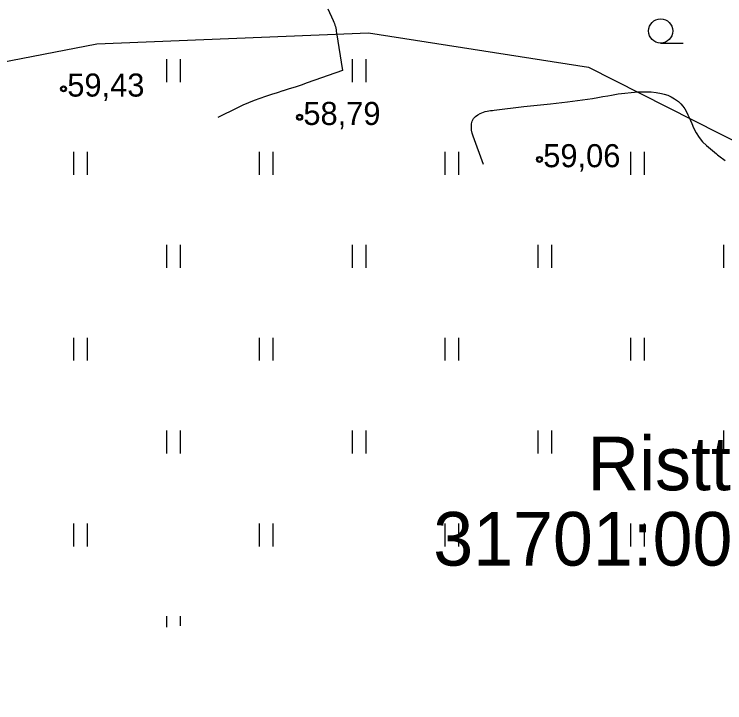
# Model space of a CAD drawing. Extents: x 532503 to 539665, y 6557663 to 6561526.
# Drawn here: x 535362.6 to 535438.1, y 6559425.3 to 6559498.5 of the extents above; entities that cross this region are included whole.
import ezdxf

# ---------------------------------------------------------------- set-up
doc = ezdxf.new("R2010")
doc.units = 0
for name, color, linetype in [('HALJASTUS', 7, 'Continuous'), ('HORISONTAAL-EH2000', 7, 'Continuous'), ('kataster', 7, 'Continuous'), ('KORGUS-EH2000', 7, 'Continuous')]:
    doc.layers.add(name, color=color, linetype=linetype)

msp = doc.modelspace()

# ---------------------------------------------------------------- linework, layer by layer
at = {"layer": 'HALJASTUS'}
for p, q in [((535431.325, 6559495.421), (535433.725, 6559495.421)), ((535378.83, 6559491.277), (535378.83, 6559493.713)), ((535380.286, 6559491.277), (535380.286, 6559493.713)), ((535398.561, 6559491.277), (535398.561, 6559493.713)), ((535400.017, 6559491.277), (535400.017, 6559493.713)), ((535368.964, 6559481.412), (535368.964, 6559483.847)), ((535370.42, 6559481.412), (535370.42, 6559483.847)), ((535388.695, 6559481.412), (535388.695, 6559483.847)), ((535390.151, 6559481.412), (535390.151, 6559483.847)), ((535408.426, 6559481.412), (535408.426, 6559483.847)), ((535409.882, 6559481.412), (535409.882, 6559483.847)), ((535428.157, 6559481.412), (535428.157, 6559483.847)), ((535429.613, 6559481.412), (535429.613, 6559483.847)), ((535378.83, 6559471.546), (535378.83, 6559473.982)), ((535380.286, 6559471.546), (535380.286, 6559473.982)), ((535398.561, 6559471.546), (535398.561, 6559473.982)), ((535400.017, 6559471.546), (535400.017, 6559473.982)), ((535418.292, 6559471.546), (535418.292, 6559473.982)), ((535419.748, 6559471.546), (535419.748, 6559473.982)), ((535438.022, 6559471.546), (535438.022, 6559473.982)), ((535368.964, 6559461.681), (535368.964, 6559464.116)), ((535370.42, 6559461.681), (535370.42, 6559464.116)), ((535388.695, 6559461.681), (535388.695, 6559464.116)), ((535390.151, 6559461.681), (535390.151, 6559464.116)), ((535408.426, 6559461.681), (535408.426, 6559464.116)), ((535409.882, 6559461.681), (535409.882, 6559464.116)), ((535428.157, 6559461.681), (535428.157, 6559464.116)), ((535429.613, 6559461.681), (535429.613, 6559464.116)), ((535378.83, 6559451.815), (535378.83, 6559454.251)), ((535380.286, 6559451.815), (535380.286, 6559454.251)), ((535398.561, 6559451.815), (535398.561, 6559454.251)), ((535400.017, 6559451.815), (535400.017, 6559454.251)), ((535418.292, 6559451.815), (535418.292, 6559454.251)), ((535419.748, 6559451.815), (535419.748, 6559454.251)), ((535438.022, 6559451.815), (535438.022, 6559454.251)), ((535368.964, 6559441.95), (535368.964, 6559444.386)), ((535370.42, 6559441.95), (535370.42, 6559444.386)), ((535388.695, 6559441.95), (535388.695, 6559444.386)), ((535390.151, 6559441.95), (535390.151, 6559444.386)), ((535408.426, 6559441.95), (535408.426, 6559444.386)), ((535409.882, 6559441.95), (535409.882, 6559444.386)), ((535428.157, 6559441.95), (535428.157, 6559444.386)), ((535429.613, 6559441.95), (535429.613, 6559444.386)), ((535378.83, 6559433.38), (535378.83, 6559434.52)), ((535380.286, 6559433.525), (535380.286, 6559434.52))]:
    msp.add_line(p, q, dxfattribs=at)
msp.add_lwpolyline([(535297.765, 6559425.333), (535293.237, 6559472.388), (535292.11, 6559493.515), (535294.197, 6559495.477), (535329.337, 6559492.847), (535343.026, 6559489.84), (535371.406, 6559495.352), (535400.286, 6559496.521), (535423.657, 6559492.847), (535443.189, 6559482.993), (535457.253, 6559472.555), (535466.268, 6559470.718), (535474.782, 6559472.889), (535489.806, 6559480.237), (535512.343, 6559484.747), (535525.539, 6559485.647)], dxfattribs=at)
msp.add_circle((535431.325, 6559496.701), 1.28, dxfattribs=at)
at = {"layer": 'HORISONTAAL-EH2000'}
for points in [[(535395.947, 6559499.038), (535396.536, 6559497.81), (535396.604, 6559497.653), (535396.665, 6559497.493), (535396.714, 6559497.33), (535396.756, 6559497.164), (535396.79, 6559496.996), (535396.823, 6559496.827), (535396.853, 6559496.658), (535396.881, 6559496.488), (535397.5, 6559492.5), (535393.758, 6559491.178), (535393.128, 6559490.96), (535392.496, 6559490.747), (535391.861, 6559490.541), (535391.225, 6559490.341), (535391.187, 6559490.33), (535390.569, 6559490.136), (535389.952, 6559489.939), (535389.338, 6559489.735), (535388.725, 6559489.527), (535388.117, 6559489.304), (535387.516, 6559489.066), (535386.924, 6559488.806), (535386.339, 6559488.53), (535384.26, 6559487.5)], [(535412.5, 6559482.5), (535411.392, 6559485.529), (535411.299, 6559485.848), (535411.235, 6559486.17), (535411.215, 6559486.498), (535411.223, 6559486.83), (535411.302, 6559487.133), (535411.43, 6559487.401), (535411.634, 6559487.617), (535411.889, 6559487.798), (535412.157, 6559487.931), (535412.331, 6559488.009), (535412.508, 6559488.077), (535412.69, 6559488.131), (535412.875, 6559488.176), (535413.063, 6559488.211), (535413.252, 6559488.243), (535413.441, 6559488.27), (535413.631, 6559488.295), (535416.798, 6559488.663), (535417.149, 6559488.704), (535417.5, 6559488.744), (535417.851, 6559488.785), (535418.202, 6559488.825), (535418.553, 6559488.864), (535418.905, 6559488.903), (535419.256, 6559488.941), (535419.607, 6559488.978), (535421.426, 6559489.169), (535421.962, 6559489.23), (535422.498, 6559489.298), (535423.032, 6559489.374), (535423.566, 6559489.457), (535424.099, 6559489.545), (535424.631, 6559489.635), (535425.163, 6559489.727), (535425.695, 6559489.82), (535426.113, 6559489.895), (535426.808, 6559490.006), (535427.505, 6559490.101), (535428.204, 6559490.172), (535428.906, 6559490.226), (535429.191, 6559490.244), (535429.749, 6559490.253), (535430.305, 6559490.231), (535430.857, 6559490.16), (535431.406, 6559490.057), (535431.705, 6559489.988), (535432.089, 6559489.868), (535432.456, 6559489.715), (535432.797, 6559489.51), (535433.12, 6559489.272), (535433.212, 6559489.193), (535433.46, 6559488.954), (535433.687, 6559488.698), (535433.881, 6559488.418), (535434.055, 6559488.12), (535434.209, 6559487.809), (535434.358, 6559487.495), (535434.501, 6559487.178), (535434.639, 6559486.859), (535434.833, 6559486.399), (535435.1, 6559485.874), (535435.411, 6559485.381), (535435.788, 6559484.937), (535436.21, 6559484.525), (535437.244, 6559483.649), (535437.374, 6559483.543), (535437.505, 6559483.439), (535437.639, 6559483.339), (535437.776, 6559483.242), (535437.911, 6559483.143), (535438.041, 6559483.039), (535438.166, 6559482.928)]]:
    msp.add_lwpolyline(points, dxfattribs=at)
at = {"layer": 'KORGUS-EH2000'}
for centre, radius in [((535367.866, 6559490.556), 0.32), ((535367.866, 6559490.556), 0.2), ((535367.866, 6559490.556), 0.2), ((535392.955, 6559487.537), 0.32), ((535392.955, 6559487.537), 0.2), ((535392.955, 6559487.537), 0.2), ((535418.447, 6559483.052), 0.32), ((535418.447, 6559483.052), 0.2), ((535418.447, 6559483.052), 0.2)]:
    msp.add_circle(centre, radius, dxfattribs=at)

# ---------------------------------------------------------------- texts
at = {"layer": 'kataster'}
for s, p in [('Risttee', (535423.532, 6559447.905)), ('31701:001:0238', (535407.159, 6559439.905))]:
    msp.add_text(s, height=5.7, dxfattribs=at).set_placement(p)
at = {"layer": 'KORGUS-EH2000'}
for s, p in [('59,43 ', (535368.266, 6559489.731)), ('58,79 ', (535393.355, 6559486.712)), ('59,06 ', (535418.847, 6559482.227))]:
    msp.add_text(s, height=2.45, dxfattribs=at).set_placement(p)

doc.saveas('drawing.dxf')
